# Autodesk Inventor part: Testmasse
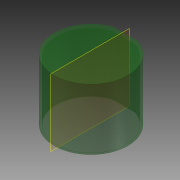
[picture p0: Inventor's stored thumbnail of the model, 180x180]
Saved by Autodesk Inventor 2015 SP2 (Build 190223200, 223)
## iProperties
Created: 2012-07
Part Number: Testmasse
Material: Allgemein
Document SubType Name: Modeling
Designer: rYan
Density: 1 g/cm^3
Mass: 524.009 g
Surface Area: 2124.25 cm^2
Volume: 524.009 cm^3
Appearance: Glatt - waldgrün Transparent
Author: rYan
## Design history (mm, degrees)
sketch "Skizze1"
  geometry: L1 (0, 120)-(0, -125) reference; L2 (-126, 0)-(126, 0) reference; L3 (-29.58, 85)-(29.58, 85); A1 r 90 centre (0, 0) between (-29.58, 85) and (29.58, 85); 1 further point
  constraints: 2 end point, 2 point on circle, 1 centre point, 1 coincident, 1 parallel
  dimensions: "d0" = 180 diameter of A1; "d1" = 85 distance between parallel lines of L2 L3
extrude "Extrusion1" new body sketch "Skizze1" distance "d2" = 150; taper "d3" = 0 deg
feature "Wandstärke1" dims "d4" = 5
workplane "Arbeitsebene1"
node "Volumenkörper1"
other parameters: "d5" = 0
